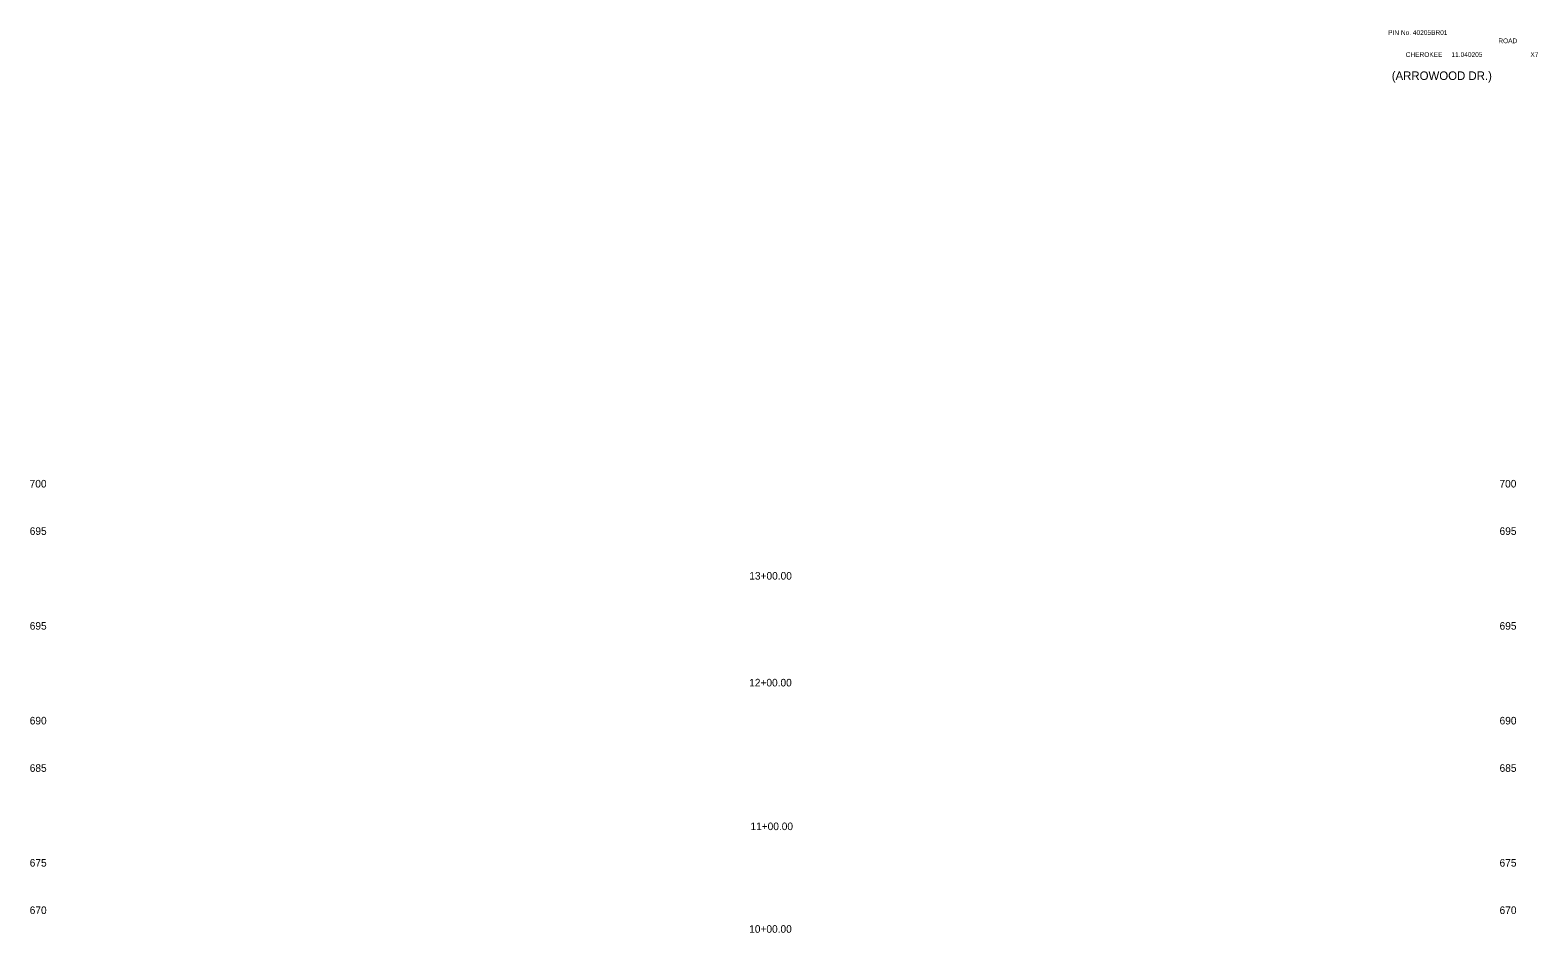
# Model space of a CAD drawing. Extents: x 1002 to 1161, y 1008 to 1103.
import ezdxf

# ---------------------------------------------------------------- set-up
doc = ezdxf.new("R2010")
doc.units = 0
for name, color, linetype in [('RD_SHT_TX', 7, 'Continuous'), ('RD_XS_TX_Elev_EX', 7, 'Continuous'), ('RD_XS_TX_Station', 7, 'Continuous')]:
    doc.layers.add(name, color=color, linetype=linetype)

msp = doc.modelspace()

# ---------------------------------------------------------------- texts
at = {"layer": 'RD_SHT_TX'}
for s, height, p in [('PIN No. 40205BR01', 0.5, (1144.72, 1102.75)), ('ROAD', 0.5, (1156.34, 1101.88)), ('CHEROKEE', 0.5, (1146.57, 1100.43)), ('11.040205 ', 0.5, (1151.4, 1100.43)), ('X7', 0.5, (1159.72, 1100.43)), ('(ARROWOOD DR.)', 0.9, (1145.1, 1098))]:
    msp.add_text(s, height=height, dxfattribs=at).set_placement(p)
at = {"layer": 'RD_XS_TX_Elev_EX'}
for s, p in [('700', (1001.46, 1055)), ('700', (1156.46, 1055)), ('695', (1001.47, 1050)), ('695', (1156.47, 1050)), ('695', (1001.47, 1040)), ('695', (1156.47, 1040)), ('690', (1001.47, 1030)), ('690', (1156.47, 1030)), ('685', (1001.47, 1025)), ('685', (1156.47, 1025)), ('675', (1001.47, 1015)), ('675', (1156.47, 1015)), ('670', (1001.47, 1010)), ('670', (1156.47, 1010))]:
    msp.add_text(s, height=0.8, dxfattribs=at).set_placement(p)
at = {"layer": 'RD_XS_TX_Station'}
for s, p in [('13+00.00', (1077.35, 1045.28)), ('12+00.00', (1077.34, 1034.01)), ('11+00.00', (1077.47, 1018.85)), ('10+00.00', (1077.34, 1008.02))]:
    msp.add_text(s, height=0.8, dxfattribs=at).set_placement(p)

doc.saveas('drawing.dxf')
